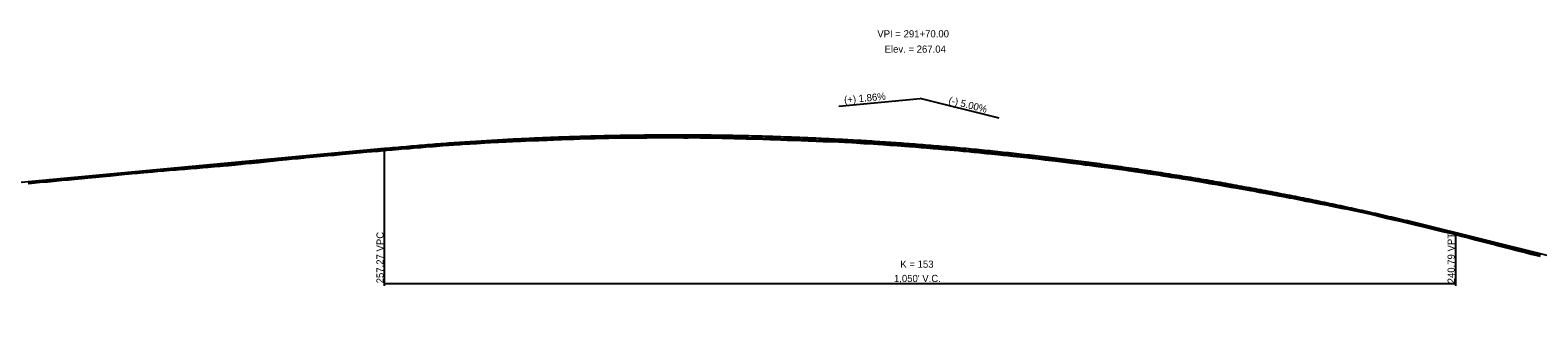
# Model space of a CAD drawing. Extents: x 1876258 to 1932803, y 754739 to 837911.
# Drawn here: x 1906661 to 1908139, y 831128 to 831407 of the extents above; entities that cross this region are included whole.
import ezdxf

# ---------------------------------------------------------------- set-up
doc = ezdxf.new("R2010")
doc.units = 0
for name, color, linetype in [('RD_DDB_GradeTX', 7, 'Continuous'), ('RD_DDB_Profile_EX', 7, 'Continuous'), ('RD_DDB_Profile_Lbl', 7, 'Continuous'), ('RD_DDB_Profile_PR', 7, 'Continuous'), ('RD_DDB_StripGrade', 7, 'Continuous'), ('RD_DDB_VCLbl', 7, 'Continuous'), ('RD_Sketch1', 7, 'Continuous')]:
    doc.layers.add(name, color=color, linetype=linetype)

msp = doc.modelspace()

# ---------------------------------------------------------------- linework, layer by layer
at = {"layer": 'RD_DDB_GradeTX'}
for p in [(1907453.4, 831332.1), (1907610.7, 831320.1)]:
    msp.add_line(p, (1907533.1, 831339.5), dxfattribs=at)
at = {"layer": 'RD_DDB_Profile_EX'}
for points in [[(1906872.2, 831275.6), (1906877.7, 831276.1), (1906884.6, 831276.9), (1906887.4, 831277.1), (1906892.8, 831277.7), (1906899, 831278.3), (1906904.4, 831278.9), (1906911.9, 831279.7), (1906917.2, 831280.2), (1906923.4, 831280.8), (1906928.9, 831281.2), (1906930.9, 831281.5), (1906938.5, 831282.3), (1906945.2, 831282.9), (1906952.1, 831283.5), (1906958.5, 831284.1), (1906966.6, 831284.9), (1906970.5, 831285.3), (1906974.1, 831285.6), (1906980.8, 831286.2), (1906984.5, 831286.5), (1906990.7, 831287.1), (1906995.4, 831287.5), (1907001.7, 831288), (1907006.9, 831288.5), (1907010.3, 831288.8), (1907015.4, 831289.2), (1907022.1, 831289.7), (1907024.7, 831290), (1907032.1, 831290.6), (1907036.9, 831291.1), (1907043.5, 831291.6), (1907048.5, 831292.1), (1907051, 831292.3), (1907055.6, 831292.6), (1907062.1, 831293), (1907065.1, 831293.3), (1907071.1, 831293.9), (1907075.7, 831294.2), (1907081.7, 831294.4), (1907087.5, 831294.9), (1907091.6, 831295.2), (1907098.1, 831295.5), (1907106.4, 831296), (1907111.9, 831296.4), (1907119.8, 831296.8), (1907127.2, 831297.1), (1907133.5, 831297.4), (1907141.3, 831297.8), (1907146.2, 831298), (1907153.4, 831298.2), (1907159.2, 831298.4), (1907167.5, 831298.8), (1907173.8, 831299), (1907181.6, 831299.3), (1907185.8, 831299.5), (1907193.5, 831299.7), (1907199.5, 831299.9), (1907208.3, 831300.2), (1907214.4, 831300.4), (1907224.2, 831300.6), (1907227.8, 831300.6), (1907232.7, 831300.8), (1907241.7, 831300.9), (1907246.7, 831301), (1907259.7, 831301.1), (1907265, 831301.1), (1907269.8, 831301.2), (1907281.2, 831301.2), (1907283.4, 831301.2), (1907289.3, 831301.2), (1907294.2, 831301.2), (1907301.4, 831301.1), (1907305.8, 831301.1), (1907310.4, 831301.2), (1907317.5, 831301.1), (1907321.9, 831301.1), (1907328.8, 831301), (1907332, 831300.9), (1907338.9, 831300.7), (1907345.8, 831300.5), (1907350.8, 831300.4), (1907355.1, 831300.3), (1907357.6, 831300.2), (1907362.5, 831300.1), (1907372.1, 831299.9), (1907378.8, 831299.7), (1907386, 831299.4), (1907390.9, 831299.3), (1907396.6, 831299.1), (1907402.8, 831298.8), (1907407.4, 831298.7), (1907412, 831298.5), (1907416.5, 831298.4), (1907423.3, 831298.1), (1907425.8, 831298), (1907431.3, 831297.8), (1907438.1, 831297.5), (1907444.1, 831297.3), (1907453.4, 831296.9), (1907458.8, 831296.7)], [(1907458.8, 831296.7), (1907466, 831296.3), (1907470.7, 831296), (1907478, 831295.5), (1907482.9, 831295.3), (1907491.6, 831294.7), (1907496.6, 831294.4), (1907503.4, 831293.9), (1907505.9, 831293.7), (1907510.5, 831293.3), (1907518, 831292.8), (1907522.7, 831292.4), (1907528.6, 831292), (1907534.1, 831291.6), (1907537, 831291.3), (1907539.2, 831291.1), (1907545.9, 831290.6), (1907550.6, 831290.1), (1907557.2, 831289.6), (1907562.2, 831289.2), (1907570.6, 831288.4), (1907575.2, 831288), (1907578.2, 831287.7), (1907585.7, 831286.9), (1907590.6, 831286.4), (1907598.2, 831285.7), (1907603, 831285.3), (1907609.6, 831284.6), (1907614.9, 831284.1), (1907616.9, 831283.8), (1907623.9, 831283.1), (1907631.1, 831282.3), (1907637.6, 831281.6), (1907643, 831280.9), (1907649.1, 831280.2), (1907655.8, 831279.4), (1907665.3, 831278.4), (1907670.8, 831277.7), (1907678, 831276.7), (1907682.8, 831276.1), (1907689.4, 831275.3), (1907694.9, 831274.6), (1907697.1, 831274.4), (1907705.3, 831273.3), (1907710.5, 831272.6), (1907716.4, 831271.8), (1907721.3, 831271.2), (1907728.1, 831270.2), (1907733.6, 831269.4), (1907737, 831268.9), (1907739.6, 831268.6), (1907746, 831267.6), (1907751.1, 831266.8), (1907756.1, 831266), (1907761.2, 831265.3), (1907766.8, 831264.5), (1907771.4, 831263.8), (1907775.9, 831263.1), (1907779.2, 831262.5), (1907785.3, 831261.6), (1907790.6, 831260.8), (1907797.4, 831259.8), (1907802.7, 831258.9), (1907808.9, 831257.8), (1907817, 831256.3), (1907824.3, 831255.1), (1907830.9, 831253.9), (1907837.5, 831252.7), (1907842.7, 831251.8), (1907848.2, 831250.9), (1907853.6, 831249.9), (1907857, 831249.3), (1907859.9, 831248.8), (1907865.1, 831247.8), (1907871.3, 831246.6), (1907876.6, 831245.6), (1907883.2, 831244.4), (1907888.9, 831243.3), (1907895, 831242.1), (1907898, 831241.6), (1907906, 831240), (1907911.3, 831238.8), (1907916.1, 831238), (1907921.7, 831237), (1907926.8, 831236), (1907931.4, 831235.1), (1907935.4, 831234.3), (1907946.2, 831232), (1907952.4, 831230.8), (1907958.3, 831229.5), (1907964.4, 831228.3), (1907970.7, 831226.9), (1907979.1, 831225), (1907985.2, 831223.5), (1907991.7, 831221.9), (1907997.6, 831220.6), (1908004, 831219.2), (1908010.5, 831217.6), (1908018.5, 831215.7), (1908025.6, 831214), (1908032.2, 831212.4)], [(1906658.6, 831256.2), (1906661.9, 831256.5), (1906670.4, 831257.3), (1906673.7, 831257.7), (1906677.5, 831257.9), (1906686.4, 831258.8), (1906691.6, 831259.3), (1906698.3, 831259.9), (1906704, 831260.4), (1906711.3, 831261.1), (1906717, 831261.7), (1906724.9, 831262.5), (1906731.4, 831263.1), (1906739.2, 831263.8), (1906744.9, 831264.3), (1906750.4, 831264.9), (1906753.5, 831265.2), (1906760.6, 831265.9), (1906765.9, 831266.4), (1906772.1, 831267), (1906780.7, 831267.7), (1906785.9, 831268.2), (1906791.8, 831268.6), (1906797.2, 831269.1), (1906803.6, 831269.7), (1906806.7, 831269.9), (1906812.3, 831270.3), (1906818.1, 831270.8), (1906824.2, 831271.3), (1906829.8, 831271.8), (1906835.1, 831272.2), (1906841.4, 831272.7), (1906846.8, 831273.2), (1906849.8, 831273.5), (1906855.2, 831273.9), (1906861.5, 831274.5), (1906867.1, 831275.1), (1906872.2, 831275.6)], [(1908032.2, 831212.4), (1908038.5, 831210.8), (1908045.2, 831209.2), (1908051.6, 831207.6), (1908058.3, 831206), (1908063.9, 831204.5), (1908072, 831202.4), (1908077.4, 831201), (1908084.2, 831199.2), (1908092, 831197.2), (1908097, 831196), (1908100.5, 831195), (1908106.9, 831193.4), (1908113.4, 831191.8), (1908119.6, 831190.1), (1908126.5, 831188.4), (1908132.2, 831186.9), (1908136.6, 831185.9), (1908140.9, 831184.8)]]:
    msp.add_lwpolyline(points, dxfattribs=at)
at = {"layer": 'RD_DDB_Profile_PR'}
for p, q in [((1906248.1, 831220), (1907008.1, 831290.7)), ((1908058.1, 831208.2), (1908378.1, 831128.2))]:
    msp.add_line(p, q, dxfattribs=at)
msp.add_spline([(1907008.1, 831290.7), (1907029.1, 831292.5), (1907050.1, 831294.3), (1907071.1, 831295.9), (1907092.1, 831297.3), (1907113.1, 831298.6), (1907134.1, 831299.8), (1907155.1, 831300.8), (1907176.1, 831301.7), (1907197.1, 831302.4), (1907218.1, 831303), (1907239.1, 831303.4), (1907260.1, 831303.7), (1907281.1, 831303.9), (1907302.1, 831303.9), (1907323.1, 831303.8), (1907344.1, 831303.5), (1907365.1, 831303.1), (1907386.1, 831302.5), (1907407.1, 831301.8), (1907428.1, 831300.9), (1907449.1, 831299.9), (1907470.1, 831298.8), (1907491.1, 831297.5), (1907512.1, 831296.1), (1907533.1, 831294.5), (1907554.1, 831292.8), (1907575.1, 831290.9), (1907596.1, 831288.9), (1907617.1, 831286.7), (1907638.1, 831284.4), (1907659.1, 831282), (1907680.1, 831279.4), (1907701.1, 831276.7), (1907722.1, 831273.8), (1907743.1, 831270.8), (1907764.1, 831267.6), (1907785.1, 831264.3), (1907806.1, 831260.9), (1907827.1, 831257.3), (1907848.1, 831253.5), (1907869.1, 831249.7), (1907890.1, 831245.6), (1907911.1, 831241.5), (1907932.1, 831237.2), (1907953.1, 831232.7), (1907974.1, 831228.1), (1907995.1, 831223.3), (1908016.1, 831218.5), (1908037.1, 831213.4), (1908058.1, 831208.2)], degree=3, dxfattribs=at)
at = {"layer": 'RD_DDB_VCLbl'}
for p, q in [((1907008.1, 831155.7), (1907008.1, 831290.7)), ((1908058.1, 831155.7), (1908058.1, 831208.2)), ((1907008.1, 831158.2), (1908058.1, 831158.2))]:
    msp.add_line(p, q, dxfattribs=at)
at = {"layer": 'RD_Sketch1'}
msp.add_lwpolyline([(1906658.5, 831257.5), (1906661.8, 831257.8), (1906670.3, 831258.6), (1906673.6, 831258.9), (1906677.4, 831259.2), (1906686.3, 831260), (1906691.5, 831260.5), (1906698.2, 831261.2), (1906703.9, 831261.7), (1906711.1, 831262.3), (1906716.9, 831262.9), (1906724.7, 831263.7), (1906731.3, 831264.4), (1906739.1, 831265), (1906744.7, 831265.5), (1906750.2, 831266.2), (1906753.4, 831266.5), (1906760.5, 831267.1), (1906765.8, 831267.7), (1906772, 831268.2), (1906780.6, 831269), (1906785.8, 831269.5), (1906791.7, 831269.9), (1906797.1, 831270.3), (1906803.5, 831270.9), (1906806.6, 831271.1), (1906812.2, 831271.5), (1906818, 831272.1), (1906824.1, 831272.6), (1906829.7, 831273), (1906835, 831273.4), (1906841.3, 831274), (1906846.7, 831274.4), (1906849.7, 831274.7), (1906855.1, 831275.2), (1906861.4, 831275.8), (1906867, 831276.3), (1906872.1, 831276.8), (1906877.6, 831277.4), (1906884.5, 831278.1), (1906887.3, 831278.3), (1906892.6, 831278.9), (1906898.9, 831279.6), (1906904.2, 831280.1), (1906911.8, 831281), (1906917, 831281.5), (1906923.3, 831282), (1906928.7, 831282.5), (1906930.8, 831282.7), (1906938.4, 831283.5), (1906945.1, 831284.2), (1906952, 831284.7), (1906958.3, 831285.4), (1906966.5, 831286.2), (1906970.4, 831286.5), (1906973.9, 831286.9), (1906980.7, 831287.5), (1906984.4, 831287.8), (1906990.6, 831288.3), (1906995.3, 831288.7), (1907001.6, 831289.3), (1907006.8, 831289.7), (1907010.2, 831290), (1907015.3, 831290.4), (1907022, 831291), (1907024.6, 831291.2), (1907032, 831291.9), (1907036.7, 831292.3), (1907043.4, 831292.9), (1907048.3, 831293.3), (1907050.9, 831293.6), (1907055.5, 831293.9), (1907062, 831294.3), (1907065, 831294.5), (1907070.9, 831295.1), (1907075.6, 831295.4), (1907081.6, 831295.7), (1907087.4, 831296.1), (1907091.6, 831296.4), (1907098, 831296.8), (1907106.3, 831297.3), (1907111.8, 831297.6), (1907119.7, 831298.1), (1907127.1, 831298.3), (1907133.4, 831298.6), (1907141.2, 831299), (1907146.2, 831299.2), (1907153.3, 831299.5), (1907159.1, 831299.7), (1907167.5, 831300), (1907173.8, 831300.3), (1907181.6, 831300.6), (1907185.8, 831300.7), (1907193.4, 831301), (1907199.4, 831301.2), (1907208.3, 831301.5), (1907214.4, 831301.6), (1907224.2, 831301.8), (1907227.8, 831301.9), (1907232.7, 831302), (1907241.7, 831302.1), (1907246.7, 831302.2), (1907259.7, 831302.4), (1907265, 831302.4), (1907269.8, 831302.5), (1907281.1, 831302.4), (1907283.4, 831302.5), (1907289.3, 831302.4), (1907294.2, 831302.4), (1907301.4, 831302.4), (1907305.8, 831302.4), (1907310.4, 831302.4), (1907317.5, 831302.3), (1907321.9, 831302.3), (1907328.9, 831302.2), (1907332, 831302.2), (1907338.9, 831302), (1907345.9, 831301.8), (1907350.8, 831301.6), (1907355.1, 831301.6), (1907357.7, 831301.5), (1907362.6, 831301.4), (1907364.7, 831301.3), (1907372.1, 831301.1), (1907374.2, 831301.1), (1907378.8, 831301), (1907383.7, 831300.7), (1907386, 831300.6), (1907390.9, 831300.5), (1907393.2, 831300.5), (1907396.7, 831300.4), (1907402.8, 831300.1), (1907402.9, 831300.1), (1907407.4, 831300), (1907412.1, 831299.8), (1907412.3, 831299.8), (1907416.6, 831299.6), (1907421.9, 831299.4), (1907423.3, 831299.3), (1907425.8, 831299.2), (1907431.4, 831299.1), (1907431.4, 831299.1), (1907438.2, 831298.8), (1907440.9, 831298.7), (1907444.2, 831298.6), (1907450.5, 831298.3), (1907453.4, 831298.2), (1907458.8, 831298), (1907460, 831297.9), (1907466, 831297.6), (1907469.5, 831297.4), (1907470.8, 831297.3), (1907478.1, 831296.8), (1907479.1, 831296.7), (1907482.9, 831296.5), (1907488.6, 831296.2), (1907491.7, 831296), (1907496.7, 831295.6), (1907498.1, 831295.5), (1907503.5, 831295.1), (1907506, 831294.9), (1907507.7, 831294.8), (1907510.6, 831294.6), (1907517.2, 831294.1), (1907518.1, 831294), (1907522.8, 831293.7), (1907526.7, 831293.4), (1907528.7, 831293.3), (1907534.2, 831292.8), (1907536.3, 831292.6), (1907537.1, 831292.5), (1907539.3, 831292.4), (1907545.8, 831291.8), (1907546, 831291.8), (1907550.7, 831291.4), (1907555.3, 831291), (1907557.3, 831290.9), (1907562.3, 831290.5), (1907564.9, 831290.2), (1907570.7, 831289.7), (1907574.4, 831289.3), (1907575.3, 831289.2), (1907578.4, 831289), (1907584, 831288.4), (1907585.8, 831288.2), (1907590.7, 831287.7), (1907593.5, 831287.4), (1907598.3, 831287), (1907603, 831286.5), (1907603.1, 831286.5), (1907609.7, 831285.8), (1907612.5, 831285.6), (1907615, 831285.3), (1907617.1, 831285.1), (1907622.1, 831284.5), (1907624, 831284.3), (1907631.2, 831283.6), (1907631.6, 831283.5), (1907637.7, 831282.9), (1907641.2, 831282.4), (1907643.2, 831282.2), (1907649.2, 831281.4), (1907650.7, 831281.2), (1907656, 831280.6), (1907660.2, 831280.2), (1907665.4, 831279.6), (1907669.8, 831279.1), (1907671, 831278.9), (1907678.1, 831277.9), (1907679.3, 831277.8), (1907683, 831277.3), (1907688.8, 831276.6), (1907689.6, 831276.5), (1907695.1, 831275.9), (1907697.2, 831275.6), (1907698.4, 831275.5), (1907705.5, 831274.5), (1907707.9, 831274.2), (1907710.6, 831273.8), (1907716.6, 831273.1), (1907717.4, 831273), (1907721.5, 831272.4), (1907727, 831271.6), (1907728.3, 831271.4), (1907733.8, 831270.6), (1907736.5, 831270.2), (1907737.2, 831270.2), (1907739.7, 831269.8), (1907746, 831268.8), (1907746.2, 831268.8), (1907751.3, 831268), (1907755.6, 831267.3), (1907756.3, 831267.2), (1907761.3, 831266.5), (1907765.1, 831266), (1907767, 831265.7), (1907771.6, 831265.1), (1907774.6, 831264.5), (1907776.1, 831264.3), (1907779.4, 831263.7), (1907784.2, 831263), (1907785.5, 831262.8), (1907790.8, 831262.1), (1907793.7, 831261.6), (1907797.6, 831261), (1907803, 831260.1), (1907803.3, 831260), (1907809.1, 831259), (1907812.8, 831258.4), (1907817.2, 831257.6), (1907822.3, 831256.7), (1907824.5, 831256.3), (1907831.1, 831255.2), (1907831.8, 831255), (1907837.8, 831254), (1907841.4, 831253.3), (1907842.9, 831253.1), (1907848.4, 831252.1), (1907850.9, 831251.7), (1907853.8, 831251.2), (1907857.2, 831250.6), (1907860.1, 831250), (1907860.5, 831249.9), (1907865.3, 831249), (1907870, 831248.1), (1907871.5, 831247.9), (1907876.8, 831246.8), (1907879.5, 831246.3), (1907883.4, 831245.6), (1907889, 831244.6), (1907889.1, 831244.5), (1907895.3, 831243.3), (1907898.2, 831242.8), (1907898.6, 831242.8), (1907906.3, 831241.2), (1907908.1, 831240.8), (1907911.6, 831240.1), (1907916.3, 831239.2), (1907917.6, 831239), (1907921.9, 831238.2), (1907927, 831237.2), (1907927.2, 831237.2), (1907931.6, 831236.3), (1907935.7, 831235.5), (1907936.7, 831235.3), (1907946.3, 831233.3), (1907946.4, 831233.2), (1907952.6, 831232), (1907955.8, 831231.3), (1907958.5, 831230.8), (1907964.7, 831229.5), (1907965.3, 831229.4), (1907971, 831228.1), (1907974.9, 831227.2), (1907979.4, 831226.2), (1907984.4, 831225), (1907985.5, 831224.7), (1907992, 831223.1), (1907993.9, 831222.7), (1907997.8, 831221.8), (1908003.5, 831220.6), (1908004.3, 831220.4), (1908010.8, 831218.8), (1908013, 831218.3), (1908018.8, 831216.9), (1908022.5, 831216), (1908025.9, 831215.2), (1908032.1, 831213.7), (1908032.5, 831213.6), (1908038.8, 831212), (1908041.6, 831211.4), (1908045.5, 831210.4), (1908051.1, 831209), (1908051.9, 831208.8), (1908058.6, 831207.2), (1908060.7, 831206.6), (1908064.3, 831205.7), (1908070.2, 831204.1), (1908072.3, 831203.6), (1908077.7, 831202.2), (1908079.7, 831201.7), (1908084.5, 831200.4), (1908089.3, 831199.2), (1908092.3, 831198.4), (1908097.3, 831197.2), (1908098.8, 831196.8), (1908100.8, 831196.3), (1908107.2, 831194.6), (1908108.3, 831194.3), (1908113.7, 831193), (1908117.9, 831191.9), (1908120, 831191.3), (1908126.8, 831189.6), (1908127.4, 831189.4), (1908132.5, 831188.1), (1908136.9, 831187.1), (1908141.2, 831186)], dxfattribs=at)

# ---------------------------------------------------------------- texts
at = {"layer": 'RD_DDB_GradeTX'}
for s, rotation, p in [('(+) 1.86%', 5.3139, (1907458.9, 831334.6)), ('(-) 5.00%', 345.9638, (1907560.4, 831334.7))]:
    msp.add_text(s, height=7, rotation=rotation, dxfattribs=at).set_placement(p)
at = {"layer": 'RD_DDB_Profile_Lbl'}
for s, p in [('VPI = 291+70.00', (1907491.1, 831399.5)), ('Elev. = 267.04', (1907498.2, 831384.5))]:
    msp.add_text(s, height=7, dxfattribs=at).set_placement(p)
at = {"layer": 'RD_DDB_StripGrade'}
for s, p in [('257.27 VPC', (1907007.1, 831158.2)), ('240.79 VPT', (1908057.1, 831158.2))]:
    msp.add_text(s, height=7, rotation=90, dxfattribs=at).set_placement(p)
at = {"layer": 'RD_DDB_VCLbl'}
for s, p in [('K = 153', (1907513.7, 831173.5)), ("1,050' V.C.", (1907507.4, 831159.5))]:
    msp.add_text(s, height=7, dxfattribs=at).set_placement(p)

doc.saveas('drawing.dxf')
